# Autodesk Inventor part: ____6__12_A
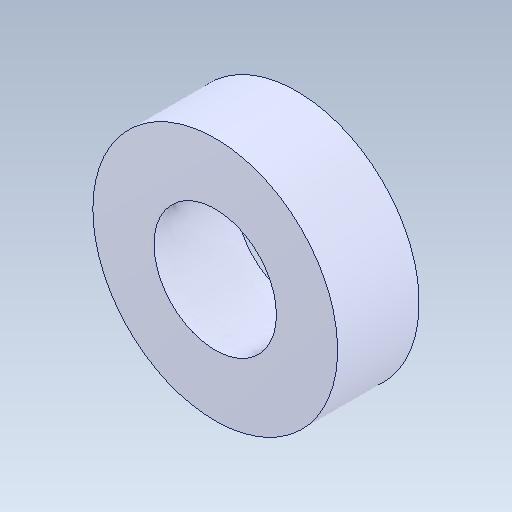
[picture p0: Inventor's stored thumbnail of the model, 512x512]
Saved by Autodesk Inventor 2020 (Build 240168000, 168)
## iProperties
Created: 2017-09
Part Number: ____6__12_A
Material: Générique
Document SubType Name: Modeling
Designer: bruno
Density: 1 g/cm^3
Appearance: Par défaut
Mass: 0.339292 g
Surface Area: 3.95841 cm^2
Volume: 0.339292 cm^3
Sending System: SolidWorks 2016
Author: bruno
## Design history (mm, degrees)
feature "Importée1"
node "Solide1"
